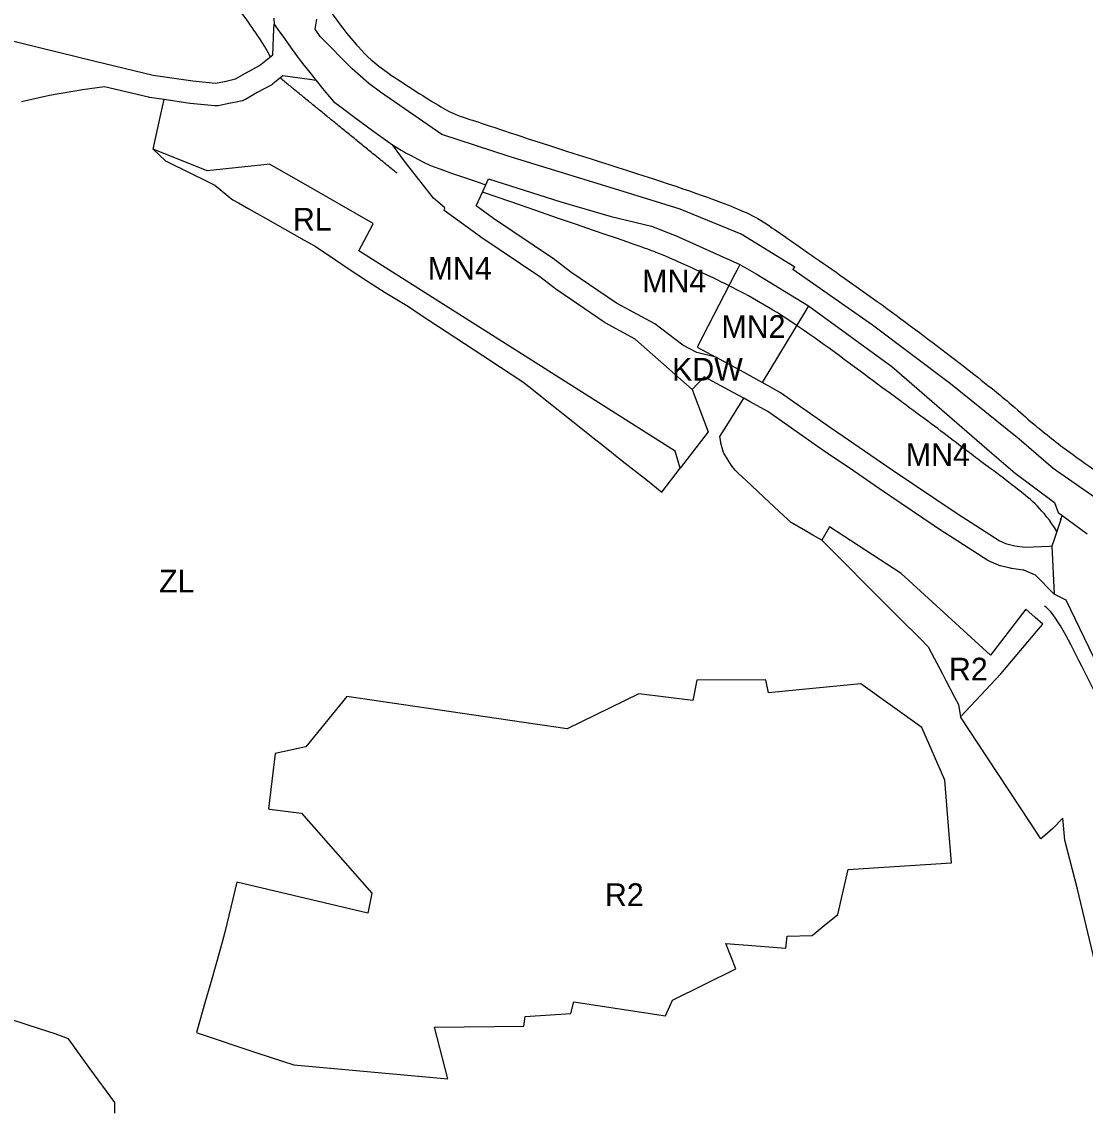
# Model space of a CAD drawing. Extents: x 7413438 to 7416393, y 5541665 to 5544118.
# Drawn here: x 7414980.3 to 7415261.6, y 5542408 to 5542694.9 of the extents above; entities that cross this region are included whole.
import ezdxf

# ---------------------------------------------------------------- set-up
doc = ezdxf.new("R2010")
doc.units = 0
for name, color, linetype in [('linie_rozgraniczajace', 7, 'Continuous'), ('linie_zabudowy_nieprzekraczalne', 7, 'Continuous'), ('oznaczenia_przeznaczen', 7, 'Continuous')]:
    doc.layers.add(name, color=color, linetype=linetype)

msp = doc.modelspace()

# ---------------------------------------------------------------- linework, layer by layer
at = {"layer": 'linie_rozgraniczajace'}
for p, q in [((7415046.96, 5542695.83), (7415047.02, 5542694.24)), ((7415057.85, 5542692.95), (7415058.35, 5542695.59)), ((7414965.17, 5542692.89), (7414980.28, 5542689.26)), ((7415046.7, 5542686.19), (7415046.93, 5542692.94)), ((7415046.93, 5542692.94), (7415047.02, 5542694.24)), ((7415047.02, 5542694.24), (7415047.4, 5542693.72)), ((7415047.4, 5542693.72), (7415048.02, 5542692.87)), ((7415048.02, 5542692.87), (7415049.78, 5542690.49)), ((7415059.19, 5542691), (7415057.85, 5542692.95)), ((7415049.78, 5542690.49), (7415050.71, 5542689.08)), ((7415067.68, 5542682.49), (7415059.19, 5542691)), ((7414980.28, 5542689.26), (7414980.29, 5542689.26)), ((7414980.29, 5542689.26), (7414999.68, 5542684.49)), ((7415050.71, 5542689.08), (7415051.79, 5542687.56)), ((7415051.79, 5542687.56), (7415051.8, 5542687.55)), ((7415051.8, 5542687.55), (7415053.17, 5542685.64)), ((7414999.68, 5542684.49), (7415015.05, 5542680.78)), ((7415043.14, 5542683.29), (7415046.7, 5542686.19)), ((7415053.17, 5542685.64), (7415053.97, 5542684.56)), ((7415053.97, 5542684.56), (7415054.89, 5542683.4)), ((7415036.84, 5542679.76), (7415039.43, 5542681.3)), ((7415039.43, 5542681.3), (7415039.52, 5542681.36)), ((7415039.52, 5542681.36), (7415039.62, 5542681.41)), ((7415039.62, 5542681.41), (7415039.64, 5542681.42)), ((7415039.64, 5542681.42), (7415043.14, 5542683.29)), ((7415054.89, 5542683.4), (7415055.4, 5542682.76)), ((7415055.4, 5542682.76), (7415057.14, 5542680.57)), ((7415072.09, 5542678.56), (7415067.68, 5542682.49)), ((7415015.05, 5542680.78), (7415025.5, 5542679.26)), ((7415025.5, 5542679.26), (7415031.5, 5542678.65)), ((7415031.5, 5542678.65), (7415034.32, 5542679.22)), ((7415034.32, 5542679.22), (7415036.84, 5542679.76)), ((7415046.58, 5542678.36), (7415046.41, 5542678.25)), ((7415046.71, 5542678.46), (7415046.58, 5542678.36)), ((7415049.31, 5542680.59), (7415046.71, 5542678.46)), ((7415056.41, 5542679.63), (7415049.31, 5542680.59)), ((7415058.13, 5542679.34), (7415056.41, 5542679.63)), ((7415057.14, 5542680.57), (7415058.13, 5542679.34)), ((7415058.13, 5542679.34), (7415059.79, 5542677.27)), ((7415075.14, 5542676.23), (7415072.09, 5542678.56)), ((7414996.34, 5542676.85), (7414987.64, 5542675.35)), ((7415002.19, 5542677.71), (7414996.34, 5542676.85)), ((7415013.78, 5542674.92), (7415002.19, 5542677.71)), ((7415042.53, 5542676.16), (7415039.48, 5542674.35)), ((7415046.22, 5542678.14), (7415042.53, 5542676.16)), ((7415046.24, 5542678.15), (7415046.22, 5542678.14)), ((7415046.41, 5542678.25), (7415046.24, 5542678.15)), ((7415059.79, 5542677.27), (7415061.14, 5542675.65)), ((7415061.14, 5542675.65), (7415062.77, 5542673.81)), ((7415091.41, 5542665.05), (7415075.14, 5542676.23)), ((7414987.64, 5542675.35), (7414980.26, 5542673.74)), ((7415013.82, 5542674.91), (7415013.78, 5542674.92)), ((7415014.01, 5542674.87), (7415013.82, 5542674.91)), ((7415014.05, 5542674.86), (7415014.01, 5542674.87)), ((7415017.91, 5542674.3), (7415014.05, 5542674.86)), ((7415017.07, 5542670.49), (7415017.91, 5542674.3)), ((7415024.7, 5542673.31), (7415017.91, 5542674.3)), ((7415024.83, 5542673.29), (7415024.7, 5542673.31)), ((7415031.34, 5542672.63), (7415024.83, 5542673.29)), ((7415031.38, 5542672.63), (7415031.34, 5542672.63)), ((7415031.57, 5542672.62), (7415031.38, 5542672.63)), ((7415031.77, 5542672.62), (7415031.57, 5542672.62)), ((7415031.96, 5542672.63), (7415031.77, 5542672.62)), ((7415032.16, 5542672.66), (7415031.96, 5542672.63)), ((7415032.24, 5542672.68), (7415032.16, 5542672.66)), ((7415035.52, 5542673.34), (7415032.24, 5542672.68)), ((7415035.56, 5542673.35), (7415035.52, 5542673.34)), ((7415037.45, 5542673.75), (7415035.56, 5542673.35)), ((7415038.58, 5542674), (7415037.45, 5542673.75)), ((7415038.65, 5542674.01), (7415038.58, 5542674)), ((7415038.84, 5542674.07), (7415038.65, 5542674.01)), ((7415039.03, 5542674.13), (7415038.84, 5542674.07)), ((7415039.21, 5542674.21), (7415039.03, 5542674.13)), ((7415039.38, 5542674.3), (7415039.21, 5542674.21)), ((7415039.48, 5542674.35), (7415039.38, 5542674.3)), ((7415062.77, 5542673.81), (7415064.73, 5542672.32)), ((7415015.02, 5542661.16), (7415017.07, 5542670.49)), ((7415064.73, 5542672.32), (7415068.01, 5542669.82)), ((7415068.01, 5542669.82), (7415073.38, 5542665.85)), ((7415073.38, 5542665.85), (7415078.32, 5542662.38)), ((7415109.2, 5542659.24), (7415091.41, 5542665.05)), ((7415015.02, 5542661.16), (7415018.31, 5542658.1)), ((7415029.31, 5542655.46), (7415015.02, 5542661.16)), ((7415081.77, 5542657.69), (7415078.32, 5542662.38)), ((7415078.32, 5542662.38), (7415080.62, 5542660.89)), ((7415080.62, 5542660.89), (7415081.42, 5542660.45)), ((7415081.42, 5542660.45), (7415081.81, 5542660.24)), ((7415081.81, 5542660.24), (7415083.09, 5542659.57)), ((7415083.09, 5542659.57), (7415085.19, 5542658.47)), ((7415085.19, 5542658.47), (7415086.58, 5542657.74)), ((7415138.22, 5542650.33), (7415109.2, 5542659.24)), ((7415018.31, 5542658.1), (7415019.19, 5542657.67)), ((7415019.19, 5542657.67), (7415029.6, 5542652.53)), ((7415044.31, 5542657.09), (7415029.31, 5542655.46)), ((7415045.82, 5542657.25), (7415044.31, 5542657.09)), ((7415054.15, 5542652.48), (7415045.82, 5542657.25)), ((7415089.17, 5542648.26), (7415081.77, 5542657.69)), ((7415086.58, 5542657.74), (7415088.43, 5542656.92)), ((7415088.43, 5542656.92), (7415091.79, 5542655.65)), ((7415091.79, 5542655.65), (7415093.68, 5542654.98)), ((7415029.6, 5542652.53), (7415031.39, 5542651.67)), ((7415073.27, 5542641.5), (7415054.15, 5542652.48)), ((7415093.68, 5542654.98), (7415099.77, 5542652.9)), ((7415099.77, 5542652.9), (7415102.79, 5542651.88)), ((7415103.02, 5542651.8), (7415103.73, 5542653.35)), ((7415103.73, 5542653.35), (7415122.88, 5542647.25)), ((7415031.39, 5542651.67), (7415031.43, 5542651.6)), ((7415031.43, 5542651.6), (7415032.19, 5542650.98)), ((7415032.19, 5542650.98), (7415035.44, 5542648.33)), ((7415100.5, 5542646.19), (7415102.14, 5542649.84)), ((7415102.14, 5542649.84), (7415103.02, 5542651.8)), ((7415102.79, 5542651.88), (7415103.02, 5542651.8)), ((7415154.43, 5542645.35), (7415138.22, 5542650.33)), ((7415035.44, 5542648.33), (7415036.11, 5542647.83)), ((7415036.11, 5542647.83), (7415037.62, 5542646.98)), ((7415037.62, 5542646.98), (7415040.33, 5542645.45)), ((7415092.14, 5542645.66), (7415089.17, 5542648.26)), ((7415122.88, 5542647.25), (7415136.17, 5542643.42)), ((7415040.33, 5542645.45), (7415044.73, 5542642.96)), ((7415092.02, 5542644.93), (7415092.14, 5542645.66)), ((7415101.6, 5542637.97), (7415092.02, 5542644.93)), ((7415105.08, 5542642.86), (7415100.5, 5542646.19)), ((7415170.51, 5542638.67), (7415154.43, 5542645.35)), ((7415044.73, 5542642.96), (7415055.02, 5542637.16)), ((7415069.42, 5542634.29), (7415073.04, 5542641.08)), ((7415073.04, 5542641.08), (7415073.27, 5542641.5)), ((7415120.69, 5542632.36), (7415105.08, 5542642.86)), ((7415136.17, 5542643.42), (7415146.88, 5542640.85)), ((7415146.88, 5542640.85), (7415153.38, 5542638.3)), ((7415153.38, 5542638.3), (7415170.19, 5542630.7)), ((7415184.75, 5542629.98), (7415170.51, 5542638.67)), ((7415055.02, 5542637.16), (7415057.93, 5542635.54)), ((7415057.93, 5542635.54), (7415063.22, 5542631.91)), ((7415101.63, 5542637.95), (7415101.6, 5542637.97)), ((7415101.69, 5542637.91), (7415101.63, 5542637.95)), ((7415117.27, 5542627.43), (7415101.69, 5542637.91)), ((7415153.11, 5542581.27), (7415069.42, 5542634.29)), ((7415063.22, 5542631.91), (7415066.84, 5542629.45)), ((7415120.75, 5542632.32), (7415120.69, 5542632.36)), ((7415120.84, 5542632.25), (7415120.75, 5542632.32)), ((7415125.5, 5542628.69), (7415120.84, 5542632.25)), ((7415170.19, 5542630.7), (7415169.41, 5542629.14)), ((7415170.19, 5542630.7), (7415174.48, 5542628.26)), ((7415184.26, 5542629.35), (7415184.75, 5542629.98)), ((7415066.84, 5542629.45), (7415072.01, 5542626.07)), ((7415121.93, 5542623.87), (7415117.27, 5542627.43)), ((7415137.61, 5542620.46), (7415125.5, 5542628.69)), ((7415168.96, 5542628.29), (7415158.95, 5542608.82)), ((7415168.99, 5542628.29), (7415168.96, 5542628.29)), ((7415168.96, 5542628.29), (7415168.96, 5542628.29)), ((7415169.41, 5542629.14), (7415168.99, 5542628.29)), ((7415174.48, 5542628.26), (7415188.36, 5542619.72)), ((7415205.33, 5542614.66), (7415184.26, 5542629.35)), ((7415072.01, 5542626.07), (7415076.44, 5542623.32)), ((7415122.02, 5542623.8), (7415121.93, 5542623.87)), ((7415122.06, 5542623.77), (7415122.02, 5542623.8)), ((7415076.44, 5542623.32), (7415082.54, 5542619.54)), ((7415134.36, 5542615.42), (7415122.06, 5542623.77)), ((7415082.54, 5542619.54), (7415085.68, 5542617.49)), ((7415147.68, 5542614.97), (7415137.61, 5542620.46)), ((7415188.36, 5542619.72), (7415187.22, 5542617.83)), ((7415188.36, 5542619.72), (7415210.43, 5542603.67)), ((7415085.68, 5542617.49), (7415102.22, 5542606.64)), ((7415134.49, 5542615.34), (7415134.36, 5542615.42)), ((7415134.61, 5542615.27), (7415134.49, 5542615.34)), ((7415142.49, 5542610.97), (7415134.61, 5542615.27)), ((7415186.76, 5542617.08), (7415176.07, 5542599.5)), ((7415187.22, 5542617.83), (7415186.76, 5542617.08)), ((7415155.15, 5542609.35), (7415147.68, 5542614.97)), ((7415225.91, 5542599.08), (7415205.33, 5542614.66)), ((7415142.62, 5542610.85), (7415142.49, 5542610.97)), ((7415157.59, 5542597.59), (7415142.62, 5542610.85)), ((7415102.22, 5542606.64), (7415106.92, 5542603.55)), ((7415158.8, 5542607.44), (7415155.15, 5542609.35)), ((7415163.83, 5542606.19), (7415158.8, 5542607.44)), ((7415158.95, 5542608.82), (7415163.83, 5542606.19)), ((7415171.32, 5542602.14), (7415163.83, 5542606.19)), ((7415106.92, 5542603.55), (7415112.8, 5542599.69)), ((7415160.78, 5542601.01), (7415157.59, 5542597.59)), ((7415168.45, 5542596.87), (7415160.78, 5542601.01)), ((7415171.34, 5542602.12), (7415171.32, 5542602.14)), ((7415176.07, 5542599.5), (7415171.34, 5542602.12)), ((7415210.43, 5542603.67), (7415236.84, 5542580.74)), ((7415112.8, 5542599.69), (7415114.42, 5542598.4)), ((7415114.42, 5542598.4), (7415120.52, 5542593.55)), ((7415180.69, 5542596.93), (7415176.07, 5542599.5)), ((7415244.11, 5542584.52), (7415225.91, 5542599.08)), ((7415157.59, 5542597.59), (7415161.82, 5542586.45)), ((7415166.74, 5542588.14), (7415171.26, 5542595.31)), ((7415171.26, 5542595.31), (7415168.45, 5542596.87)), ((7415172.94, 5542594.38), (7415171.26, 5542595.31)), ((7415180.79, 5542596.87), (7415180.69, 5542596.93)), ((7415180.95, 5542596.77), (7415180.79, 5542596.87)), ((7415194.15, 5542587.51), (7415180.95, 5542596.77)), ((7415120.52, 5542593.55), (7415126.05, 5542589.14)), ((7415177.63, 5542591.77), (7415172.94, 5542594.38)), ((7415190.72, 5542582.58), (7415177.63, 5542591.77)), ((7415126.05, 5542589.14), (7415131.32, 5542584.96)), ((7415164.93, 5542585.21), (7415166.74, 5542588.14)), ((7415197.5, 5542585.21), (7415194.15, 5542587.51)), ((7415131.32, 5542584.96), (7415134.02, 5542582.8)), ((7415161.82, 5542586.45), (7415154.4, 5542576.81)), ((7415165.07, 5542584.18), (7415164.93, 5542585.21)), ((7415165.21, 5542583.4), (7415165.07, 5542584.18)), ((7415210.53, 5542576.31), (7415197.5, 5542585.21)), ((7415253.05, 5542576.7), (7415244.11, 5542584.52)), ((7415134.02, 5542582.8), (7415139.12, 5542578.75)), ((7415154.4, 5542576.81), (7415153.11, 5542581.27)), ((7415165.87, 5542581), (7415165.21, 5542583.4)), ((7415165.97, 5542580.81), (7415165.87, 5542581)), ((7415167.14, 5542578.9), (7415165.97, 5542580.81)), ((7415190.75, 5542582.56), (7415190.72, 5542582.58)), ((7415195, 5542579.66), (7415190.75, 5542582.56)), ((7415139.12, 5542578.75), (7415145.74, 5542573.53)), ((7415168.03, 5542577.51), (7415167.14, 5542578.9)), ((7415198.82, 5542577.04), (7415195, 5542579.66)), ((7415236.84, 5542580.74), (7415243.05, 5542575.5)), ((7415149.56, 5542570.51), (7415154.4, 5542576.8)), ((7415154.4, 5542576.8), (7415154.4, 5542576.81)), ((7415168.96, 5542576.25), (7415168.03, 5542577.51)), ((7415170.01, 5542575.27), (7415168.96, 5542576.25)), ((7415171.78, 5542573.61), (7415170.01, 5542575.27)), ((7415201.65, 5542575.11), (7415198.82, 5542577.04)), ((7415207.15, 5542571.35), (7415201.65, 5542575.11)), ((7415227.67, 5542564.74), (7415210.53, 5542576.31)), ((7415243.05, 5542575.5), (7415253.41, 5542567.76)), ((7415264.06, 5542569.04), (7415253.05, 5542576.7)), ((7415145.74, 5542573.53), (7415149.56, 5542570.51)), ((7415176.51, 5542569.18), (7415171.78, 5542573.61)), ((7415207.17, 5542571.34), (7415207.15, 5542571.35)), ((7415224.34, 5542559.75), (7415207.17, 5542571.34)), ((7415180.59, 5542565.36), (7415176.51, 5542569.18)), ((7415253.41, 5542567.76), (7415254.38, 5542565.11)), ((7415182.79, 5542563.3), (7415180.59, 5542565.36)), ((7415238.83, 5542557.61), (7415227.67, 5542564.74)), ((7415254.38, 5542565.11), (7415255.33, 5542564.35)), ((7415255.33, 5542564.35), (7415255.07, 5542563.29)), ((7415255.33, 5542564.35), (7415262.03, 5542559.44)), ((7415183.42, 5542562.71), (7415182.79, 5542563.3)), ((7415183.61, 5542562.54), (7415183.42, 5542562.71)), ((7415187.58, 5542560.25), (7415183.61, 5542562.54)), ((7415193.88, 5542561.26), (7415191.91, 5542557.76)), ((7415212.83, 5542548.99), (7415193.88, 5542561.26)), ((7415255.06, 5542563.27), (7415253.21, 5542557.65)), ((7415255.07, 5542563.29), (7415254.95, 5542563.37)), ((7415254.95, 5542563.37), (7415255.06, 5542563.28)), ((7415255.06, 5542563.28), (7415255.06, 5542563.27)), ((7415189.54, 5542559.13), (7415187.58, 5542560.25)), ((7415191.91, 5542557.76), (7415189.54, 5542559.13)), ((7415224.41, 5542559.71), (7415224.34, 5542559.75)), ((7415226.66, 5542558.27), (7415224.41, 5542559.71)), ((7415235.79, 5542552.43), (7415226.66, 5542558.27)), ((7415191.91, 5542557.76), (7415193.55, 5542556.11)), ((7415191.91, 5542557.76), (7415191.91, 5542557.76)), ((7415193.55, 5542556.11), (7415198.39, 5542551.24)), ((7415240.81, 5542556.72), (7415238.83, 5542557.61)), ((7415242.97, 5542556.2), (7415240.81, 5542556.72)), ((7415245.69, 5542555.83), (7415242.97, 5542556.2)), ((7415252.06, 5542556.09), (7415245.69, 5542555.83)), ((7415252.74, 5542556.21), (7415252.06, 5542556.09)), ((7415253.21, 5542557.65), (7415252.74, 5542556.21)), ((7415252.74, 5542556.21), (7415253.34, 5542543.45)), ((7415235.84, 5542552.4), (7415235.79, 5542552.43)), ((7415236.01, 5542552.3), (7415235.84, 5542552.4)), ((7415236.17, 5542552.23), (7415236.01, 5542552.3)), ((7415238.61, 5542551.13), (7415236.17, 5542552.23)), ((7415198.39, 5542551.24), (7415203.48, 5542546.11)), ((7415238.62, 5542551.12), (7415238.61, 5542551.13)), ((7415238.8, 5542551.05), (7415238.62, 5542551.12)), ((7415238.99, 5542550.99), (7415238.8, 5542551.05)), ((7415239.14, 5542550.94), (7415238.99, 5542550.99)), ((7415241.72, 5542550.33), (7415239.14, 5542550.94)), ((7415241.76, 5542550.32), (7415241.72, 5542550.33)), ((7415241.95, 5542550.29), (7415241.76, 5542550.32)), ((7415242.01, 5542550.28), (7415241.95, 5542550.29)), ((7415245.13, 5542549.85), (7415242.01, 5542550.28)), ((7415245.27, 5542549.83), (7415245.13, 5542549.85)), ((7415245.3, 5542549.83), (7415245.27, 5542549.83)), ((7415246.59, 5542549.34), (7415245.3, 5542549.83)), ((7415248.38, 5542548.5), (7415246.59, 5542549.34)), ((7415236.51, 5542527.37), (7415212.83, 5542548.99)), ((7415253.34, 5542543.45), (7415248.38, 5542548.5)), ((7415203.48, 5542546.11), (7415208.86, 5542540.7)), ((7415208.86, 5542540.7), (7415212.58, 5542537)), ((7415256.53, 5542541.94), (7415253.34, 5542543.45)), ((7415263.79, 5542526.73), (7415256.53, 5542541.94)), ((7415245.88, 5542539.49), (7415236.51, 5542527.37)), ((7415248.34, 5542537.31), (7415245.88, 5542539.49)), ((7415212.58, 5542537), (7415217.87, 5542531.72)), ((7415239.27, 5542522.4), (7415249.69, 5542534.87)), ((7415250.35, 5542535.54), (7415248.34, 5542537.31)), ((7415249.69, 5542534.87), (7415250.35, 5542535.54)), ((7415217.87, 5542531.72), (7415220.03, 5542529.57)), ((7415220.03, 5542529.57), (7415221.63, 5542526.52)), ((7415221.63, 5542526.52), (7415223.77, 5542522.43)), ((7415158.8, 5542520.74), (7415157.76, 5542515.36)), ((7415177.06, 5542520.83), (7415158.8, 5542520.74)), ((7415177.74, 5542517.43), (7415177.06, 5542520.83)), ((7415223.77, 5542522.43), (7415224.68, 5542520.69)), ((7415224.68, 5542520.69), (7415226.93, 5542516.38)), ((7415228.57, 5542511.06), (7415239.27, 5542522.4)), ((7415194.04, 5542519), (7415177.74, 5542517.43)), ((7415202.19, 5542519.79), (7415194.04, 5542519)), ((7415218.37, 5542508.22), (7415202.19, 5542519.79)), ((7415066.25, 5542516.46), (7415055.4, 5542503.12)), ((7415105.85, 5542510.59), (7415066.25, 5542516.46)), ((7415143.48, 5542517.11), (7415124.52, 5542507.83)), ((7415157.76, 5542515.36), (7415143.48, 5542517.11)), ((7415226.93, 5542516.38), (7415228.01, 5542514.31)), ((7415228.01, 5542514.31), (7415228.57, 5542511.06)), ((7415124.52, 5542507.83), (7415105.85, 5542510.59)), ((7415235.72, 5542500.16), (7415228.57, 5542511.06)), ((7415224.38, 5542494.29), (7415218.37, 5542508.22)), ((7415047.35, 5542501.34), (7415045.52, 5542486.67)), ((7415055.4, 5542503.12), (7415047.35, 5542501.34)), ((7415246.95, 5542483.07), (7415235.72, 5542500.16)), ((7415225.37, 5542482.1), (7415224.38, 5542494.29)), ((7415045.52, 5542486.67), (7415045.77, 5542486.63)), ((7415045.77, 5542486.63), (7415054.29, 5542485.57)), ((7415054.29, 5542485.57), (7415072.85, 5542464.42)), ((7415255.63, 5542484.23), (7415252.96, 5542481.47)), ((7415256.19, 5542478.38), (7415255.63, 5542484.23)), ((7415226.16, 5542472.4), (7415225.37, 5542482.1)), ((7415249.8, 5542478.73), (7415246.95, 5542483.07)), ((7415252.96, 5542481.47), (7415250.21, 5542479.08)), ((7415250.21, 5542479.08), (7415249.8, 5542478.73)), ((7415259.52, 5542465.47), (7415256.19, 5542478.38)), ((7415208.33, 5542471.27), (7415226.16, 5542472.4)), ((7415196.09, 5542458.78), (7415198.81, 5542470.66)), ((7415198.81, 5542470.66), (7415208.33, 5542471.27)), ((7415037.15, 5542467.32), (7415033.98, 5542454.08)), ((7415071.83, 5542459.14), (7415037.15, 5542467.32)), ((7415072.85, 5542464.42), (7415071.83, 5542459.14)), ((7415264.12, 5542446.23), (7415259.52, 5542465.47)), ((7415192.54, 5542455.85), (7415196.09, 5542458.78)), ((7415189.34, 5542453.19), (7415192.51, 5542455.82)), ((7415192.51, 5542455.82), (7415192.55, 5542455.82)), ((7415192.55, 5542455.82), (7415192.54, 5542455.85)), ((7415033.98, 5542454.08), (7415033.28, 5542451.39)), ((7415182.4, 5542449.86), (7415182.72, 5542452.98)), ((7415182.72, 5542452.98), (7415189.34, 5542453.19)), ((7415033.28, 5542451.39), (7415031.77, 5542446.08)), ((7415169.11, 5542444.41), (7415166.46, 5542451.12)), ((7415166.46, 5542451.12), (7415171.12, 5542450.76)), ((7415171.12, 5542450.76), (7415171.19, 5542450.67)), ((7415171.19, 5542450.67), (7415171.19, 5542450.75)), ((7415171.19, 5542450.75), (7415182.4, 5542449.86)), ((7415031.77, 5542446.08), (7415030.26, 5542440.79)), ((7415152.41, 5542436.05), (7415169.11, 5542444.41)), ((7415030.26, 5542440.79), (7415028.74, 5542435.42)), ((7415028.74, 5542435.42), (7415028.1, 5542433.17)), ((7415125.54, 5542432.59), (7415126.33, 5542435.63)), ((7415126.33, 5542435.63), (7415150.52, 5542431.93)), ((7415150.52, 5542431.93), (7415152.41, 5542436.05)), ((7414984.96, 5542428.51), (7414972.59, 5542432.52)), ((7415028.1, 5542433.17), (7415026.51, 5542427.58)), ((7415113.1, 5542429.19), (7415113.4, 5542431.78)), ((7415113.4, 5542431.78), (7415125.54, 5542432.59)), ((7415089.42, 5542428.99), (7415113.1, 5542429.19)), ((7415092.99, 5542415.25), (7415089.42, 5542428.99)), ((7414989.1, 5542427.17), (7414984.96, 5542428.51)), ((7414992.64, 5542425.85), (7414989.1, 5542427.17)), ((7414998.31, 5542418.06), (7414992.64, 5542425.85)), ((7415026.51, 5542427.58), (7415026.71, 5542427.43)), ((7415026.71, 5542427.43), (7415042.68, 5542422.11)), ((7415042.68, 5542422.11), (7415052.25, 5542418.98)), ((7415004.9, 5542409), (7414998.31, 5542418.06)), ((7415052.25, 5542418.98), (7415092.99, 5542415.25)), ((7415004.88, 5542406.23), (7415004.9, 5542409))]:
    msp.add_line(p, q, dxfattribs=at)
at = {"layer": 'linie_zabudowy_nieprzekraczalne'}
for points, degree in [([(7415046.04, 5542685.6), (7415044.89, 5542688.05), (7415038.46, 5542697.69), (7415034.17, 5542702.2), (7415025.08, 5542708.44), (7415009, 5542715.33), (7414995.57, 5542721.52), (7414970.94, 5542731.05), (7414970.88, 5542731.08), (7414970.52, 5542731.25), (7414970.35, 5542731.34), (7414938.93, 5542744.38), (7414938.9, 5542744.39), (7414938.71, 5542744.46), (7414901.8, 5542759.46), (7414901.63, 5542759.53), (7414901.27, 5542759.7), (7414900.93, 5542759.89), (7414900.6, 5542760.11), (7414900.45, 5542760.22), (7414898.5, 5542761.69), (7414898.34, 5542761.82), (7414898.1, 5542762.02), (7414893.84, 5542765.85), (7414883.77, 5542771.83), (7414883.71, 5542771.87), (7414883.61, 5542771.93), (7414880.89, 5542773.67), (7414878.59, 5542776.46), (7414860.73, 5542786.52), (7414855.46, 5542791.34), (7414852.65, 5542792.67), (7414844.32, 5542798.84), (7414832.02, 5542808.01), (7414822.28, 5542811.7), (7414810.95, 5542816.79), (7414794.96, 5542824.01), (7414775.51, 5542832.34), (7414755.97, 5542839.09), (7414752.31, 5542840.07), (7414750.38, 5542840.58), (7414740.26, 5542842.54), (7414740.13, 5542842.57), (7414739.26, 5542842.76)], 3), ([(7415060.2, 5542700.03), (7415063.8, 5542694.82), (7415069.96, 5542687.2), (7415074.97, 5542682.48), (7415094.07, 5542670.45), (7415095.67, 5542670.19), (7415115.82, 5542663.31), (7415160.33, 5542649.35), (7415173.61, 5542643.76), (7415176.31, 5542642.11), (7415190.15, 5542632.51), (7415210.39, 5542618.3), (7415230.16, 5542603.31), (7415243.83, 5542592.3), (7415246.54, 5542589.46), (7415257.35, 5542580.95), (7415265.92, 5542574.94), (7415271.31, 5542571.58), (7415279.78, 5542563.89), (7415291.54, 5542557.48)], 3), ([(7415079.56, 5542654.81), (7415059.9, 5542670.75), (7415048.65, 5542680.04)], 2), ([(7415254.05, 5542560.05), (7415250.53, 5542565.87), (7415243.32, 5542571.51), (7415237.29, 5542576.23), (7415234.68, 5542577.94), (7415222.15, 5542587.67), (7415206.72, 5542598.9), (7415183.61, 5542616.29), (7415167.44, 5542625.31), (7415151.02, 5542632.74), (7415147.83, 5542633.99), (7415144.62, 5542635.22), (7415102.12, 5542649.81)], 3), ([(7415354.02, 5542157.54), (7415351.12, 5542172.84), (7415343.57, 5542209.73), (7415339.4, 5542229.81), (7415336.1, 5542245.87), (7415329.78, 5542276.17), (7415325.62, 5542295.99), (7415324.08, 5542302.96), (7415325.54, 5542310.25), (7415322.96, 5542316.74), (7415320.29, 5542324.11), (7415316.96, 5542335.38), (7415310.62, 5542361.08), (7415303.17, 5542393.62), (7415293.51, 5542434.1), (7415288.48, 5542454.95), (7415286.07, 5542465.01), (7415283.42, 5542473.12), (7415276.7, 5542491.46), (7415272.35, 5542501.51), (7415261.71, 5542522.05), (7415253.51, 5542538.9), (7415250.76, 5542540.28)], 3)]:
    msp.add_open_spline(points, degree=degree, dxfattribs=at)

# ---------------------------------------------------------------- texts
at = {"layer": 'oznaczenia_przeznaczen'}
for s, p in [('RL', (7415052, 5542639.64)), ('MN4', (7415087.65, 5542626.7)), ('MN4', (7415144.38, 5542623.31)), ('MN2', (7415165.33, 5542611.27)), ('KDW', (7415152.29, 5542599.99)), ('MN4', (7415214.1, 5542577.4)), ('ZL', (7415016.61, 5542543.93)), ('R2', (7415225.5, 5542520.66)), ('R2', (7415134.52, 5542460.99))]:
    msp.add_text(s, height=6, dxfattribs=at).set_placement(p)

doc.saveas('drawing.dxf')
